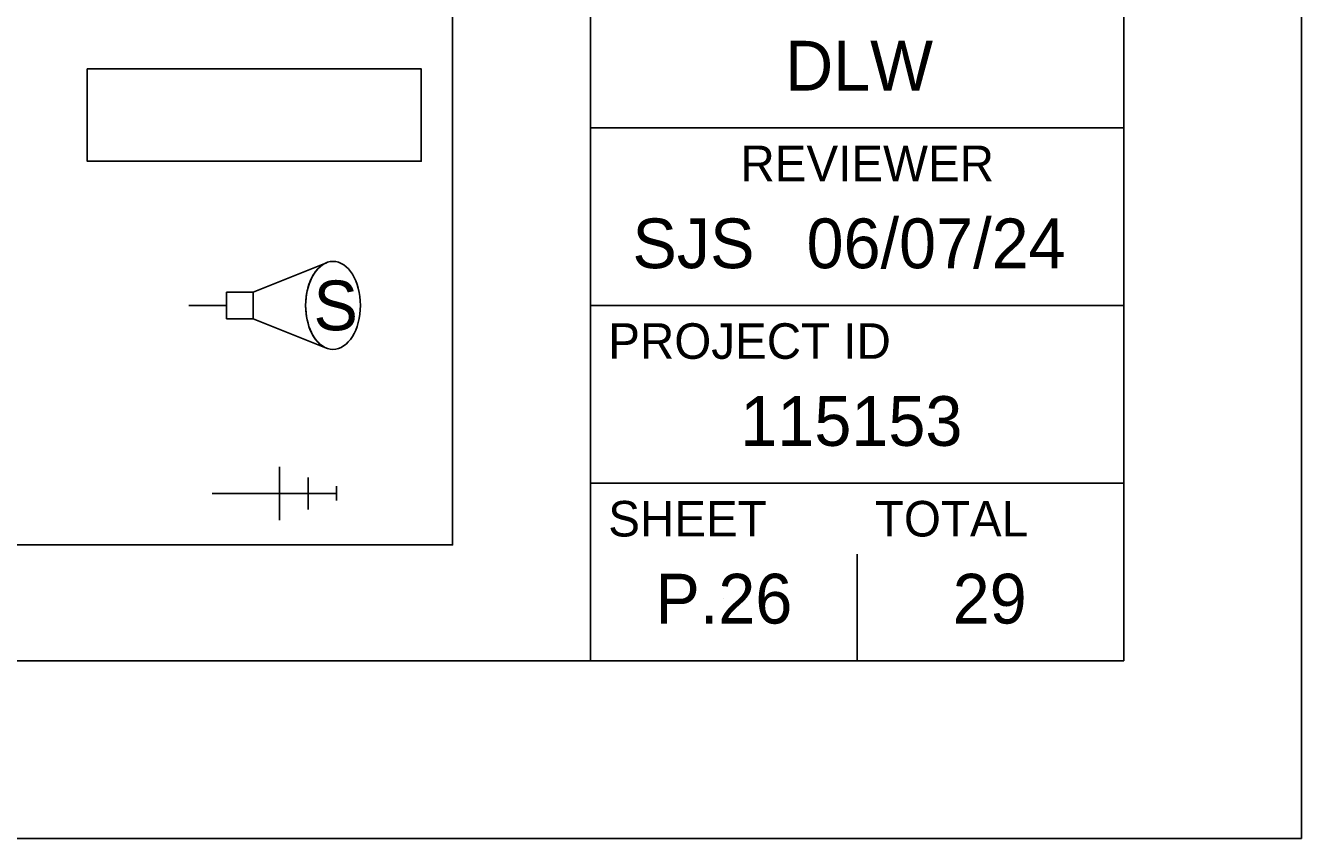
# Model space of a CAD drawing. Extents: x 0 to 34, y 0 to 22.
# Drawn here: x 30.411 to 34, y 0 to 2.288 of the extents above; entities that cross this region are included whole.
import ezdxf

# ---------------------------------------------------------------- set-up
doc = ezdxf.new("R2010")
doc.units = 0
for name, color, linetype in [('PM_P_Stop_Line', 7, 'Continuous'), ('SC_Scratch1', 7, 'Continuous'), ('SG_P_Heads', 7, 'Continuous'), ('SG_P_Mast_Arm', 7, 'Continuous'), ('SN_P_Signs', 7, 'Continuous'), ('UT_X_Electric', 7, 'Continuous')]:
    doc.layers.add(name, color=color, linetype=linetype)

msp = doc.modelspace()

# ---------------------------------------------------------------- linework, layer by layer
at = {"layer": 'PM_P_Stop_Line'}
for p, q in [((32, 0.5), (32, 21.5)), ((32, 2), (33.5, 2)), ((32, 1.5), (33.5, 1.5)), ((32, 1), (33.5, 1))]:
    msp.add_line(p, q, dxfattribs=at)
msp.add_lwpolyline([(1.5, 21.5), (33.5, 21.5), (33.5, 0.5), (1.5, 0.5)], close=True, dxfattribs=at)
at = {"layer": 'SC_Scratch1'}
for p, q in [((32.75, 0.5), (32.75, 0.8)), ((32.375, 0.675), (32.375, 0.675))]:
    msp.add_line(p, q, dxfattribs=at)
msp.add_lwpolyline([(26.8738, 7.5516), (26.8738, 0.8263), (31.6119, 0.8263), (31.612, 7.5516), (31.612, 7.5516)], close=True, dxfattribs=at)
at = {"layer": 'SG_P_Heads'}
msp.add_lwpolyline([(0, 0), (34, 0), (34, 22), (0, 22)], close=True, dxfattribs=at)
at = {"layer": 'SG_P_Mast_Arm'}
for p, q in [((31.0514, 1.538), (31.2572, 1.6206)), ((31.2572, 1.6206), (31.0514, 1.538)), ((31.0514, 1.538), (31.0514, 1.463)), ((30.8703, 1.5005), (30.9764, 1.5005)), ((31.0514, 1.463), (31.2571, 1.3801)), ((31.0514, 1.463), (31.2571, 1.3801))]:
    msp.add_line(p, q, dxfattribs=at)
msp.add_lwpolyline([(30.9764, 1.538), (30.9764, 1.463), (31.0514, 1.463), (31.0514, 1.538)], close=True, dxfattribs=at)
msp.add_lwpolyline([(30.9764, 1.538), (30.9764, 1.463), (31.0514, 1.463), (31.0514, 1.538), (30.9764, 1.538)], dxfattribs=at)
msp.add_ellipse((31.2758, 1.5003), major_axis=(-0.0001, -0.1239), ratio=0.621318, dxfattribs=at)
msp.add_ellipse((31.2758, 1.5003), major_axis=(-0.0001, -0.1239), ratio=0.621318, start_param=3.386213, end_param=6.038231, dxfattribs=at)
at = {"layer": 'SN_P_Signs'}
for p, q in [((31.1255, 0.8962), (31.1255, 1.0462)), ((31.2055, 0.9262), (31.2055, 1.0162)), ((30.9355, 0.9712), (31.2855, 0.9712)), ((31.2855, 0.9912), (31.2855, 0.9512))]:
    msp.add_line(p, q, dxfattribs=at)
at = {"layer": 'UT_X_Electric'}
msp.add_lwpolyline([(30.5844, 2.1657), (31.5239, 2.1657), (31.5239, 1.9059), (30.5844, 1.9059)], close=True, dxfattribs=at)
msp.add_lwpolyline([(30.5844, 2.1657), (31.5239, 2.1657), (31.5239, 1.9059), (30.5844, 1.9059)], close=True, dxfattribs=at)

# ---------------------------------------------------------------- texts
at = {"layer": 'SC_Scratch1'}
for s, height, p in [('DLW', 0.14, (32.5474, 2.105)), ('REVIEWER', 0.1, (32.4218, 1.85)), ('SJS', 0.14, (32.118, 1.605)), ('06/07/24', 0.14, (32.6078, 1.605)), ('PROJECT ID', 0.1, (32.05, 1.35)), ('115153', 0.14, (32.4215, 1.105)), ('SHEET', 0.1, (32.05, 0.85)), ('TOTAL', 0.1, (32.8, 0.85)), ('P.26', 0.14, (32.1827, 0.605)), ('29', 0.14, (33.0188, 0.605))]:
    msp.add_text(s, height=height, dxfattribs=at).set_placement(p)
at = {"layer": 'SG_P_Mast_Arm'}
msp.add_text('S', height=0.14, dxfattribs=at).set_placement((31.2209, 1.4303))

doc.saveas('drawing.dxf')
